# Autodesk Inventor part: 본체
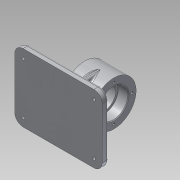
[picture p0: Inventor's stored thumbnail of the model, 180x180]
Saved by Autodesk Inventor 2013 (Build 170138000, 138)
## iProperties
Created: 2019-09
Part Number: 본체
Material: 알루미늄 6061
Document SubType Name: Modeling
Designer: Administrator
Density: 1 g/cm^3
Author: Administrator
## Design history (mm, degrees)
sketch "스케치1"
  geometry: L1 (-63, -49)-(63, -49); L2 (63, -49)-(63, 49); L3 (63, 49)-(-63, 49); L4 (-63, 49)-(-63, -49); L5 (-63, -49)-(63, 49); L6 (63, -49)-(-63, 49); 1 further point
  constraints: 12 end point, 2 midpoint, 2 parallel, 1 horizontal, 1 perpendicular
  dimensions: "d0" = 126 distance of L1.start L1.end; "d2" = 98 distance of L1.end L2.end
extrude "돌출1" new body sketch "스케치1" distance "d3" = 9; taper "d4" = 0 deg
fillet "모깎기1" dims "d5" = 12
fillet "모깎기2" dims "d6" = 12
hole "구멍1" diameter "d9" = 4.5; stored, may be unused: countersink angle "d13" = 90 deg, drill point angle "d15" = 118 deg; dims "d7" = 10, "d8" = 10, "d10" = 6, "d11" = 8, "d12" = 4.4, "d14" = 10
hole "구멍2" diameter "d18" = 4.5; stored, may be unused: countersink angle "d22" = 90 deg, drill point angle "d24" = 118 deg; dims "d16" = 10, "d17" = 10, "d19" = 6, "d20" = 8, "d21" = 4.4, "d23" = 10
hole "구멍3" diameter "d27" = 4.5; stored, may be unused: countersink angle "d31" = 90 deg, drill point angle "d33" = 118 deg; dims "d25" = 10, "d26" = 10, "d28" = 6, "d29" = 8, "d30" = 4.4, "d32" = 10
hole "구멍4" diameter "d36" = 4.5; stored, may be unused: countersink angle "d40" = 90 deg, drill point angle "d42" = 118 deg; dims "d34" = 10, "d35" = 10, "d37" = 6, "d38" = 8, "d39" = 4.4, "d41" = 10
node "작업 평면1"
sketch "스케치2"
  geometry: L1 (-12, 0)-(-12, 9) reference; L2 (-12, 9)-(86, 9) reference; L3 (86, 9)-(86, 0) reference; L4 (86, 0)-(-12, 0) reference; L5 (-12, 0)-(-12, 9) reference; L6 (-12, 9)-(86, 9) reference; L7 (86, 9)-(86, 0) reference; L8 (86, 0)-(-12, 0) reference; L9 (-12, 0)-(-12, 9) reference; C1 r 32 at (24, 59); 1 further point
  constraints: 1 centre point
  dimensions: "d44" = 64 diameter of C1; "d71" = 36 distance from line of L1 C1.centre; "d72" = 59 distance from line of L4 C1.centre
extrude "돌출2" join sketch "스케치2" stored distance "d45" = 42; taper "d46" = 0 deg
sketch "스케치4" dims "d47" = 52
  geometry: C1 r 32 at (0, 0) reference; 3 further points
  constraints: 1 coincident, 1 vertical alignment, 2 other
hole "구멍5" sketch "스케치4" at (0, 26) diameter "d48" = 3.459; stored, may be unused: countersink angle "d52" = 90 deg, drill point angle "d54" = 118 deg; dims "d49" = 8, "d50" = 4, "d51" = 2, "d53" = 10
sketch "스케치5"
  geometry: C1 r 32 at (0, 0) reference; C2 r 21 at (0, 0); 1 further point
  constraints: 1 centre point, 1 coincident
  dimensions: "d58" = 42 diameter of C2
extrude "돌출3" cut sketch "스케치5" distance "d59" = 15; taper "d60" = 0 deg
sketch "스케치6"
  geometry: C1 r 21 at (0, 0) reference; C2 r 18 at (0, 0); 1 further point
  constraints: 1 centre point, 1 coincident
  dimensions: "d61" = 36 diameter of C2
extrude "돌출4" cut sketch "스케치6" distance "d62" = 30; taper "d63" = 0 deg
sketch "스케치7"
  geometry: C1 r 32 at (0, 0) reference; C2 r 21 at (0, 0); 1 further point
  constraints: 1 centre point, 1 coincident
  dimensions: "d64" = 42 diameter of C2
extrude "돌출5" cut sketch "스케치7" distance "d65" = 15; taper "d66" = 0 deg
node "작업 평면2"
chamfer "모따기1" distance "d67" = 1; stored, may be unused: second distance "d68" = 2, angle "d69" = 45 deg
fillet "모깎기3" dims "d70" = 0.3
sketch "스케치9"
  geometry: 1 further point
sketch "스케치11"
  geometry: L1 (51, 49)-(-51, 49) reference; L2 (-63, 37)-(-63, -37) reference; L3 (-51, -49)-(51, -49) reference; L4 (63, -37)-(63, 37) reference; C1 r 4 at (51, -37) reference; C2 r 4 at (-51, -37) reference; C3 r 4 at (51, 37) reference; C4 r 4 at (-51, 37) reference; A1 r 12 centre (51, 37) between (63, 37) and (51, 49) reference; A2 r 12 centre (-51, 37) between (-51, 49) and (-63, 37) reference; A3 r 12 centre (-51, -37) between (-63, -37) and (-51, -49) reference; A4 r 12 centre (51, -37) between (51, -49) and (63, -37) reference; 1 further point
sketch "스케치13"
  geometry: L1 (-60, -37)-(-60, 37) reference; L2 (51, -46)-(-51, -46) reference; L3 (60, 37)-(60, -37) reference; L4 (-51, 46)-(51, 46) reference; L5 (4, 46)-(-4, 46); L6 (-4, 46)-(-4, -20); L7 (-4, -20)-(4, -20); L8 (4, -20)-(4, 46); L9 (4, 46)-(-4, -20); L10 (-4, 46)-(4, -20); L11 (-63, 37)-(-63, -37) reference; L12 (-51, -49)-(51, -49) reference; L13 (51, -49)-(-51, -49) reference; L14 (-63, -37)-(-63, 37) reference; L15 (-51, 49)-(51, 49) reference; L16 (63, 37)-(63, -37) reference; C1 r 4 at (-51, 37) reference; C2 r 4 at (51, 37) reference; C3 r 4 at (-51, -37) reference; C4 r 4 at (51, -37) reference; C5 r 4 at (51, -37) reference; C6 r 4 at (-51, -37) reference; C7 r 4 at (51, 37) reference; C8 r 4 at (-51, 37) reference; A1 r 9 centre (-51, 37) between (-51, 46) and (-60, 37) reference; A2 r 9 centre (-51, -37) between (-60, -37) and (-51, -46) reference; A3 r 9 centre (51, -37) between (51, -46) and (60, -37) reference; A4 r 9 centre (51, 37) between (60, 37) and (51, 46) reference; A5 r 12 centre (51, -37) between (51, -49) and (63, -37) reference; A6 r 12 centre (-51, -37) between (-63, -37) and (-51, -49) reference; A7 r 12 centre (-51, 37) between (-51, 49) and (-63, 37) reference; A8 r 12 centre (51, 37) between (63, 37) and (51, 49) reference; 3 further points
  constraints: 12 end point, 4 midpoint, 2 parallel, 1 horizontal, 1 perpendicular
  dimensions: "d83" = 8 distance of L5.start L5.end; "d84" = 62 distance from line of L12 point (0, 13)
  node "절단 모서리 투영5"
sketch "스케치15"
  geometry: L1 (51, -46)-(-51, -46); L2 (-63, 37)-(-63, -37) reference; L3 (-51, -49)-(51, -49) reference; 2 further points
  constraints: 2 end point, 1 other
  dimensions: "d86" = 62 distance from line of L2 point (-1, -39); "d87" = 10 distance from line of point (-1, -39) L3
feature "엠보싱1" sketch "스케치15" dims "d16" = 10, "d17" = 10, "d88" = 0.5, "d89" = 0
sketch "스케치16"
  geometry: L1 (-60, -37)-(-60, 37) reference; L2 (51, -46)-(-51, -46) reference; L3 (60, 37)-(60, -37) reference; L4 (-51, 46)-(51, 46) reference; L5 (-16.014, -39.22)-(-16.014, -37.911) reference; L6 (-18.999, -38.115)-(-19.046, -37.742) reference; L7 (-15.566, -37.511)-(-15.566, -41.14) reference; L8 (-15.566, -41.14)-(-18.463, -41.14) reference; L9 (-18.463, -41.14)-(-18.463, -40.767) reference; L10 (-18.463, -40.767)-(-16.014, -40.767) reference; L11 (-16.014, -40.767)-(-16.014, -39.594) reference; L12 (-16.014, -39.594)-(-18.198, -39.594) reference; L13 (-18.198, -39.594)-(-18.198, -39.22) reference; L14 (-18.198, -39.22)-(-16.014, -39.22) reference; L15 (-13.449, -41.71)-(-13.449, -37.334) reference; L16 (-13.449, -37.334)-(-12.995, -37.334) reference; L17 (-12.995, -37.334)-(-12.995, -41.921) reference; L18 (-12.995, -41.921)-(-13.354, -41.921) reference; L19 (-12.289, -41.609)-(-12.289, -37.585) reference; L20 (-12.289, -37.585)-(-11.834, -37.585) reference; L21 (-11.834, -37.585)-(-11.834, -40.007) reference; L22 (-11.834, -40.007)-(-10.803, -40.007) reference; L23 (-10.803, -40.007)-(-10.803, -40.353) reference; L24 (-10.803, -40.353)-(-11.834, -40.353) reference; L25 (-11.834, -40.353)-(-11.834, -41.846) reference; L26 (-11.834, -41.846)-(-12.208, -41.846) reference; L27 (-13.592, -36.371)-(-13.592, -35.998) reference; L28 (-13.592, -35.998)-(-9.27, -35.998) reference; L29 (-9.27, -35.998)-(-9.27, -37.911) reference; L30 (-9.27, -37.911)-(-9.602, -37.911) reference; L31 (-9.718, -37.708)-(-9.718, -36.371) reference; L32 (-9.718, -36.371)-(-13.592, -36.371) reference; L33 (-11.414, -38.752)-(-11.109, -38.406) reference; L34 (-8.415, -38.203)-(-8.103, -38.542) reference; L35 (-9.67, -41.656)-(-10.071, -41.656) reference; L36 (-7.031, -38.02)-(-7.479, -38.02) reference; L37 (-7.438, -39.926)-(-6.984, -39.926) reference; L38 (-2.526, -41.385)-(-2.526, -40.971) reference; L39 (-2.526, -40.971)-(-0.966, -40.971) reference; L40 (-0.966, -40.971)-(-0.966, -36.385) reference; L41 (-0.966, -36.385)-(-0.512, -36.385) reference; L42 (-0.512, -36.385)-(-0.512, -40.971) reference; L43 (-0.512, -40.971)-(1.042, -40.971) reference; L44 (1.042, -40.971)-(1.042, -41.385) reference; L45 (1.042, -41.385)-(-2.526, -41.385) reference; L46 (9.095, -38.149)-(7.284, -38.149) reference; L47 (7.284, -38.149)-(7.284, -36.025) reference; L48 (7.284, -36.025)-(7.745, -36.025) reference; L49 (7.745, -36.025)-(7.745, -37.775) reference; L50 (7.745, -37.775)-(11.578, -37.775) reference; L51 (11.578, -37.775)-(11.578, -38.149) reference; L52 (11.578, -38.149)-(9.55, -38.149) reference; L53 (9.55, -38.149)-(9.55, -39.37) reference; L54 (9.55, -39.37)-(12.311, -39.37) reference; L55 (12.311, -39.37)-(12.311, -39.743) reference; L56 (12.311, -39.743)-(7.942, -39.743) reference; L57 (7.657, -41.412)-(11.463, -41.412) reference; L58 (11.463, -41.412)-(11.463, -41.792) reference; L59 (11.463, -41.792)-(7.175, -41.792) reference; L60 (7.446, -39.743)-(6.307, -39.743) reference; L61 (6.307, -39.743)-(6.307, -39.37) reference; L62 (6.307, -39.37)-(9.095, -39.37) reference; L63 (9.095, -39.37)-(9.095, -38.149) reference; L64 (1.917, -36.385)-(2.474, -37.911) reference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; C1 r 4 at (51, -37) reference; C2 r 4 at (-51, -37) reference; C3 r 4 at (51, 37) reference; C4 r 4 at (-51, 37) reference; C5 r 4 at (51, -37) reference; C6 r 4 at (-51, -37) reference; C7 r 4 at (51, 37) reference; C8 r 4 at (-51, 37) reference; A1 r 9 centre (-51, 37) between (-51, 46) and (-60, 37) reference; A2 r 9 centre (-51, -37) between (-60, -37) and (-51, -46) reference; A3 r 9 centre (51, -37) between (51, -46) and (60, -37) reference; A4 r 9 centre (51, 37) between (60, 37) and (51, 46) reference; A5 r 12 centre (51, -37) between (51, -49) and (63, -37) reference; A6 r 12 centre (-51, -37) between (-63, -37) and (-51, -49) reference; A7 r 12 centre (-51, 37) between (-51, 49) and (-63, 37) reference; A8 r 12 centre (51, 37) between (63, 37) and (51, 49) reference; 61 further points
  constraints: 144 other
  node "절단 모서리 투영7"
sketch "스케치17"
  geometry: L1 (51, 49)-(-51, 49) reference; L2 (-63, 37)-(-63, -37) reference; L3 (-51, -49)-(51, -49) reference; L4 (63, -37)-(63, 37) reference; L5 (-16.014, -39.22)-(-16.014, -37.911) reference; L6 (-18.999, -38.115)-(-19.046, -37.742) reference; L7 (-15.566, -37.511)-(-15.566, -41.14) reference; L8 (-15.566, -41.14)-(-18.463, -41.14) reference; L9 (-18.463, -41.14)-(-18.463, -40.767) reference; L10 (-18.463, -40.767)-(-16.014, -40.767) reference; L11 (-16.014, -40.767)-(-16.014, -39.594) reference; L12 (-16.014, -39.594)-(-18.198, -39.594) reference; L13 (-18.198, -39.594)-(-18.198, -39.22) reference; L14 (-18.198, -39.22)-(-16.014, -39.22) reference; L15 (-13.449, -41.71)-(-13.449, -37.334) reference; L16 (-13.449, -37.334)-(-12.995, -37.334) reference; L17 (-12.995, -37.334)-(-12.995, -41.921) reference; L18 (-12.995, -41.921)-(-13.354, -41.921) reference; L19 (-12.289, -41.609)-(-12.289, -37.585) reference; L20 (-12.289, -37.585)-(-11.834, -37.585) reference; L21 (-11.834, -37.585)-(-11.834, -40.007) reference; L22 (-11.834, -40.007)-(-10.803, -40.007) reference; L23 (-10.803, -40.007)-(-10.803, -40.353) reference; L24 (-10.803, -40.353)-(-11.834, -40.353) reference; L25 (-11.834, -40.353)-(-11.834, -41.846) reference; L26 (-11.834, -41.846)-(-12.208, -41.846) reference; L27 (-13.592, -36.371)-(-13.592, -35.998) reference; L28 (-13.592, -35.998)-(-9.27, -35.998) reference; L29 (-9.27, -35.998)-(-9.27, -37.911) reference; L30 (-9.27, -37.911)-(-9.602, -37.911) reference; L31 (-9.718, -37.708)-(-9.718, -36.371) reference; L32 (-9.718, -36.371)-(-13.592, -36.371) reference; L33 (-11.414, -38.752)-(-11.109, -38.406) reference; L34 (-8.415, -38.203)-(-8.103, -38.542) reference; L35 (-9.67, -41.656)-(-10.071, -41.656) reference; L36 (-7.031, -38.02)-(-7.479, -38.02) reference; L37 (-7.438, -39.926)-(-6.984, -39.926) reference; L38 (-2.526, -41.385)-(-2.526, -40.971) reference; L39 (-2.526, -40.971)-(-0.966, -40.971) reference; L40 (-0.966, -40.971)-(-0.966, -36.385) reference; L41 (-0.966, -36.385)-(-0.512, -36.385) reference; L42 (-0.512, -36.385)-(-0.512, -40.971) reference; L43 (-0.512, -40.971)-(1.042, -40.971) reference; L44 (1.042, -40.971)-(1.042, -41.385) reference; L45 (1.042, -41.385)-(-2.526, -41.385) reference; L46 (9.095, -38.149)-(7.284, -38.149) reference; L47 (7.284, -38.149)-(7.284, -36.025) reference; L48 (7.284, -36.025)-(7.745, -36.025) reference; L49 (7.745, -36.025)-(7.745, -37.775) reference; L50 (7.745, -37.775)-(11.578, -37.775) reference; L51 (11.578, -37.775)-(11.578, -38.149) reference; L52 (11.578, -38.149)-(9.55, -38.149) reference; L53 (9.55, -38.149)-(9.55, -39.37) reference; L54 (9.55, -39.37)-(12.311, -39.37) reference; L55 (12.311, -39.37)-(12.311, -39.743) reference; L56 (12.311, -39.743)-(7.942, -39.743) reference; L57 (7.657, -41.412)-(11.463, -41.412) reference; L58 (11.463, -41.412)-(11.463, -41.792) reference; L59 (11.463, -41.792)-(7.175, -41.792) reference; L60 (7.446, -39.743)-(6.307, -39.743) reference; L61 (6.307, -39.743)-(6.307, -39.37) reference; L62 (6.307, -39.37)-(9.095, -39.37) reference; L63 (9.095, -39.37)-(9.095, -38.149) reference; L64 (1.917, -36.385)-(2.474, -37.911) reference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; C1 r 4 at (-51, 37) reference; C2 r 4 at (51, 37) reference; C3 r 4 at (-51, -37) reference; C4 r 4 at (51, -37) reference; A1 r 12 centre (51, 37) between (63, 37) and (51, 49) reference; A2 r 12 centre (-51, 37) between (-51, 49) and (-63, 37) reference; A3 r 12 centre (-51, -37) between (-63, -37) and (-51, -49) reference; A4 r 12 centre (51, -37) between (51, -49) and (63, -37) reference; 54 further points
  constraints: 68 other
sketch "스케치18"
  geometry: L1 (-63, 37)-(-63, -37) reference; L2 (-51, -49)-(51, -49) reference; L3 (63, -37)-(63, 37) reference; L4 (-16.014, -39.22)-(-16.014, -37.911) reference; L5 (-18.999, -38.115)-(-19.046, -37.742) reference; L6 (-15.566, -37.511)-(-15.566, -41.14) reference; L7 (-15.566, -41.14)-(-18.463, -41.14) reference; L8 (-18.463, -41.14)-(-18.463, -40.767) reference; L9 (-18.463, -40.767)-(-16.014, -40.767) reference; L10 (-16.014, -40.767)-(-16.014, -39.594) reference; L11 (-16.014, -39.594)-(-18.198, -39.594) reference; L12 (-18.198, -39.594)-(-18.198, -39.22) reference; L13 (-18.198, -39.22)-(-16.014, -39.22) reference; L14 (-13.449, -41.71)-(-13.449, -37.334) reference; L15 (-13.449, -37.334)-(-12.995, -37.334) reference; L16 (-12.995, -37.334)-(-12.995, -41.921) reference; L17 (-12.995, -41.921)-(-13.354, -41.921) reference; L18 (-12.289, -41.609)-(-12.289, -37.585) reference; L19 (-12.289, -37.585)-(-11.834, -37.585) reference; L20 (-11.834, -37.585)-(-11.834, -40.007) reference; L21 (-11.834, -40.007)-(-10.803, -40.007) reference; L22 (-10.803, -40.007)-(-10.803, -40.353) reference; L23 (-10.803, -40.353)-(-11.834, -40.353) reference; L24 (-11.834, -40.353)-(-11.834, -41.846) reference; L25 (-11.834, -41.846)-(-12.208, -41.846) reference; L26 (-13.592, -36.371)-(-13.592, -35.998) reference; L27 (-13.592, -35.998)-(-9.27, -35.998) reference; L28 (-9.27, -35.998)-(-9.27, -37.911) reference; L29 (-9.27, -37.911)-(-9.602, -37.911) reference; L30 (-9.718, -37.708)-(-9.718, -36.371) reference; L31 (-9.718, -36.371)-(-13.592, -36.371) reference; L32 (-11.414, -38.752)-(-11.109, -38.406) reference; L33 (-8.415, -38.203)-(-8.103, -38.542) reference; L34 (-9.67, -41.656)-(-10.071, -41.656) reference; L35 (-7.031, -38.02)-(-7.479, -38.02) reference; L36 (-7.438, -39.926)-(-6.984, -39.926) reference; L37 (-2.526, -41.385)-(-2.526, -40.971) reference; L38 (-2.526, -40.971)-(-0.966, -40.971) reference; L39 (-0.966, -40.971)-(-0.966, -36.385) reference; L40 (-0.966, -36.385)-(-0.512, -36.385) reference; L41 (-0.512, -36.385)-(-0.512, -40.971) reference; L42 (-0.512, -40.971)-(1.042, -40.971) reference; L43 (1.042, -40.971)-(1.042, -41.385) reference; L44 (1.042, -41.385)-(-2.526, -41.385) reference; L45 (9.095, -38.149)-(7.284, -38.149) reference; L46 (7.284, -38.149)-(7.284, -36.025) reference; L47 (7.284, -36.025)-(7.745, -36.025) reference; L48 (7.745, -36.025)-(7.745, -37.775) reference; L49 (7.745, -37.775)-(11.578, -37.775) reference; L50 (11.578, -37.775)-(11.578, -38.149) reference; L51 (11.578, -38.149)-(9.55, -38.149) reference; L52 (9.55, -38.149)-(9.55, -39.37) reference; L53 (9.55, -39.37)-(12.311, -39.37) reference; L54 (12.311, -39.37)-(12.311, -39.743) reference; L55 (12.311, -39.743)-(7.942, -39.743) reference; L56 (7.657, -41.412)-(11.463, -41.412) reference; L57 (11.463, -41.412)-(11.463, -41.792) reference; L58 (11.463, -41.792)-(7.175, -41.792) reference; L59 (7.446, -39.743)-(6.307, -39.743) reference; L60 (6.307, -39.743)-(6.307, -39.37) reference; L61 (6.307, -39.37)-(9.095, -39.37) reference; L62 (9.095, -39.37)-(9.095, -38.149) reference; L63 (1.917, -36.385)-(2.474, -37.911) reference; L64 (2.474, -37.911)-(4.726, -37.911) reference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; C1 r 4 at (-51, 37) reference; C2 r 4 at (51, 37) reference; C3 r 4 at (-51, -37) reference; C4 r 4 at (51, -37) reference; A1 r 12 centre (51, 37) between (63, 37) and (51, 49) reference; A2 r 12 centre (-51, 37) between (-51, 49) and (-63, 37) reference; A3 r 12 centre (-51, -37) between (-63, -37) and (-51, -49) reference; A4 r 12 centre (51, -37) between (51, -49) and (63, -37) reference; 54 further points
  constraints: 12 end point, 2 midpoint, 2 parallel, 1 horizontal, 1 perpendicular, 68 other
  dimensions: "d97" = 8 distance of L102.end L103.end
fillet "모깎기5" dims "d99" = 3
node "작업 평면5"
sketch "스케치19"
  geometry: L1 (-59, -50)-(-54.385, -50) reference; L2 (-54.385, -50)-(-54.385, -49.5) reference; L3 (-54.385, -49.5)-(-53.971, -49.5) reference; L4 (-53.971, -49.5)-(-53.971, -50) reference; L5 (-53.971, -50)-(33, -50) reference; L6 (36, -53)-(36, -59) reference; L7 (36, -59)-(-62, -59) reference; L8 (-62, -59)-(-62, -53) reference; L9 (-32, 0)-(-32, -53); L10 (32, 0)-(32, -51.953); L11 (32, -51.953)-(-32, -53); L12 (-32, 0)-(-24.612, 7.001); L13 (-24.612, 7.001)-(-24.612, -3.123); L14 (-24.612, -3.123)-(-20.245, -18); L15 (-20.245, -18)-(-7.384, -25.977); L16 (-7.384, -25.977)-(12.019, -20.281); L17 (12.019, -20.281)-(23.435, -9.464); L18 (23.435, -9.464)-(29.304, 0); L19 (29.304, 0)-(32, 0); C1 r 18 at (0, 0) reference; A1 r 32 centre (0, 0) between (-32, 0) and (32, 0) reference; A2 r 3 centre (-59, -53) between (-59, -50) and (-62, -53) reference; A3 r 3 centre (33, -53) between (36, -53) and (33, -50) reference; 1 further point
  constraints: 22 end point, 3 vertical, 2 perpendicular, 2 point on circle, 2 tangent, 1 horizontal, 1 parallel
extrude "돌출6" join sketch "스케치19" stored distance "d100" = 8; taper "d101" = 0 deg
sketch "스케치20"
  geometry: L1 (-17, 17)-(17, 17); L2 (17, 17)-(17, 9); L3 (17, 9)-(-17, 9); L4 (-17, 9)-(-17, 17); L5 (-17, 17)-(17, 9); L6 (17, 17)-(-17, 9); L7 (-4, 45)-(4, 45) reference; L8 (4, 45)-(4, -19) reference; L9 (4, -19)-(-4, -19) reference; L10 (-4, -19)-(-4, 45) reference; L11 (60, -37)-(60, 37) reference; L12 (51, 46)-(-51, 46) reference; L13 (-60, 37)-(-60, -37) reference; L14 (-51, -46)-(51, -46) reference; L15 (-19.989, -38.997)-(-18.659, -38.997) reference; L16 (-18.659, -38.997)-(-18.659, -39.377) reference; L17 (-18.659, -39.377)-(-19.989, -39.377) reference; L18 (-19.989, -39.377)-(-19.989, -41.955) reference; L19 (-19.989, -41.955)-(-20.315, -41.955) reference; L20 (-20.45, -41.69)-(-20.45, -36.018) reference; L21 (-20.45, -36.018)-(-19.989, -36.018) reference; L22 (-19.989, -36.018)-(-19.989, -38.997) reference; L23 (12.942, -39.648)-(12.942, -39.254) reference; L24 (12.942, -39.254)-(14.061, -39.254) reference; L25 (14.061, -39.254)-(14.061, -37.511) reference; L26 (14.061, -37.511)-(14.536, -37.511) reference; L27 (14.536, -37.511)-(14.536, -42.002) reference; L28 (14.536, -42.002)-(14.231, -42.002) reference; L29 (14.061, -41.737)-(14.061, -39.648) reference; L30 (14.061, -39.648)-(12.942, -39.648) reference; L31 (13.844, -36.561)-(13.844, -36.181) reference; L32 (13.844, -36.181)-(18.193, -36.181) reference; L33 (18.193, -36.181)-(18.193, -37.809) reference; L34 (18.193, -37.809)-(17.84, -37.809) reference; L35 (17.731, -37.592)-(17.731, -36.561) reference; L36 (17.731, -36.561)-(13.844, -36.561) reference; L37 (16.374, -41.425)-(17.853, -41.425) reference; L38 (17.853, -41.425)-(17.853, -41.778) reference; L39 (17.853, -41.778)-(16.374, -41.778) reference; L40 (16.374, -41.778)-(16.374, -41.425) reference; L41 (19.047, -40.618)-(19.047, -40.971) reference; L42 (19.047, -40.971)-(15.282, -40.971) reference; L43 (15.282, -40.971)-(15.282, -40.618) reference; L44 (15.282, -40.618)-(19.047, -40.618) reference; L45 (1.917, -36.385)-(2.474, -37.911) reference; L46 (2.474, -37.911)-(4.726, -37.911) reference; L47 (4.726, -37.911)-(5.296, -36.385) reference; L48 (5.296, -36.385)-(5.777, -36.385) reference; L49 (5.777, -36.385)-(3.878, -41.385) reference; L50 (3.878, -41.385)-(3.335, -41.385) reference; L51 (3.335, -41.385)-(1.436, -36.385) reference; L52 (1.436, -36.385)-(1.917, -36.385) reference; L53 (3.613, -40.896)-(4.57, -38.325) reference; L54 (4.57, -38.325)-(2.636, -38.325) reference; L55 (2.636, -38.325)-(3.613, -40.896) reference; L56 (9.095, -38.149)-(7.284, -38.149) reference; L57 (7.284, -38.149)-(7.284, -36.025) reference; L58 (7.284, -36.025)-(7.745, -36.025) reference; L59 (7.745, -36.025)-(7.745, -37.775) reference; L60 (7.745, -37.775)-(11.578, -37.775) reference; L61 (11.578, -37.775)-(11.578, -38.149) reference; L62 (11.578, -38.149)-(9.55, -38.149) reference; L63 (9.55, -38.149)-(9.55, -39.37) reference; L64 (9.55, -39.37)-(12.311, -39.37) reference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; C1 r 4 at (51, -37) reference; C2 r 4 at (-51, -37) reference; C3 r 4 at (51, 37) reference; C4 r 4 at (-51, 37) reference; A1 r 9 centre (51, 37) between (60, 37) and (51, 46) reference; A2 r 9 centre (-51, 37) between (-51, 46) and (-60, 37) reference; A3 r 9 centre (-51, -37) between (-60, -37) and (-51, -46) reference; A4 r 9 centre (51, -37) between (51, -46) and (60, -37) reference; 64 further points
  constraints: 16 end point, 4 midpoint, 2 parallel, 1 horizontal, 1 perpendicular, 76 other
  dimensions: "d102" = 8 distance of L3.end L1.start; "d104" = 34 distance of L2.end L3.end
extrude "돌출7" join sketch "스케치20" stored distance "d105" = 8; taper "d106" = 0 deg
fillet "모깎기6" dims "d107" = 3
fillet "모깎기7" dims "d108" = 3
node "솔리드1"
pattern_circular "원형 패턴1" dims angle "d56" = 360 deg
mirror "대칭1"
node "절단 모서리 투영1"
node "절단 모서리 투영2"
node "절단 모서리 투영8"
node "절단 모서리 투영9"
